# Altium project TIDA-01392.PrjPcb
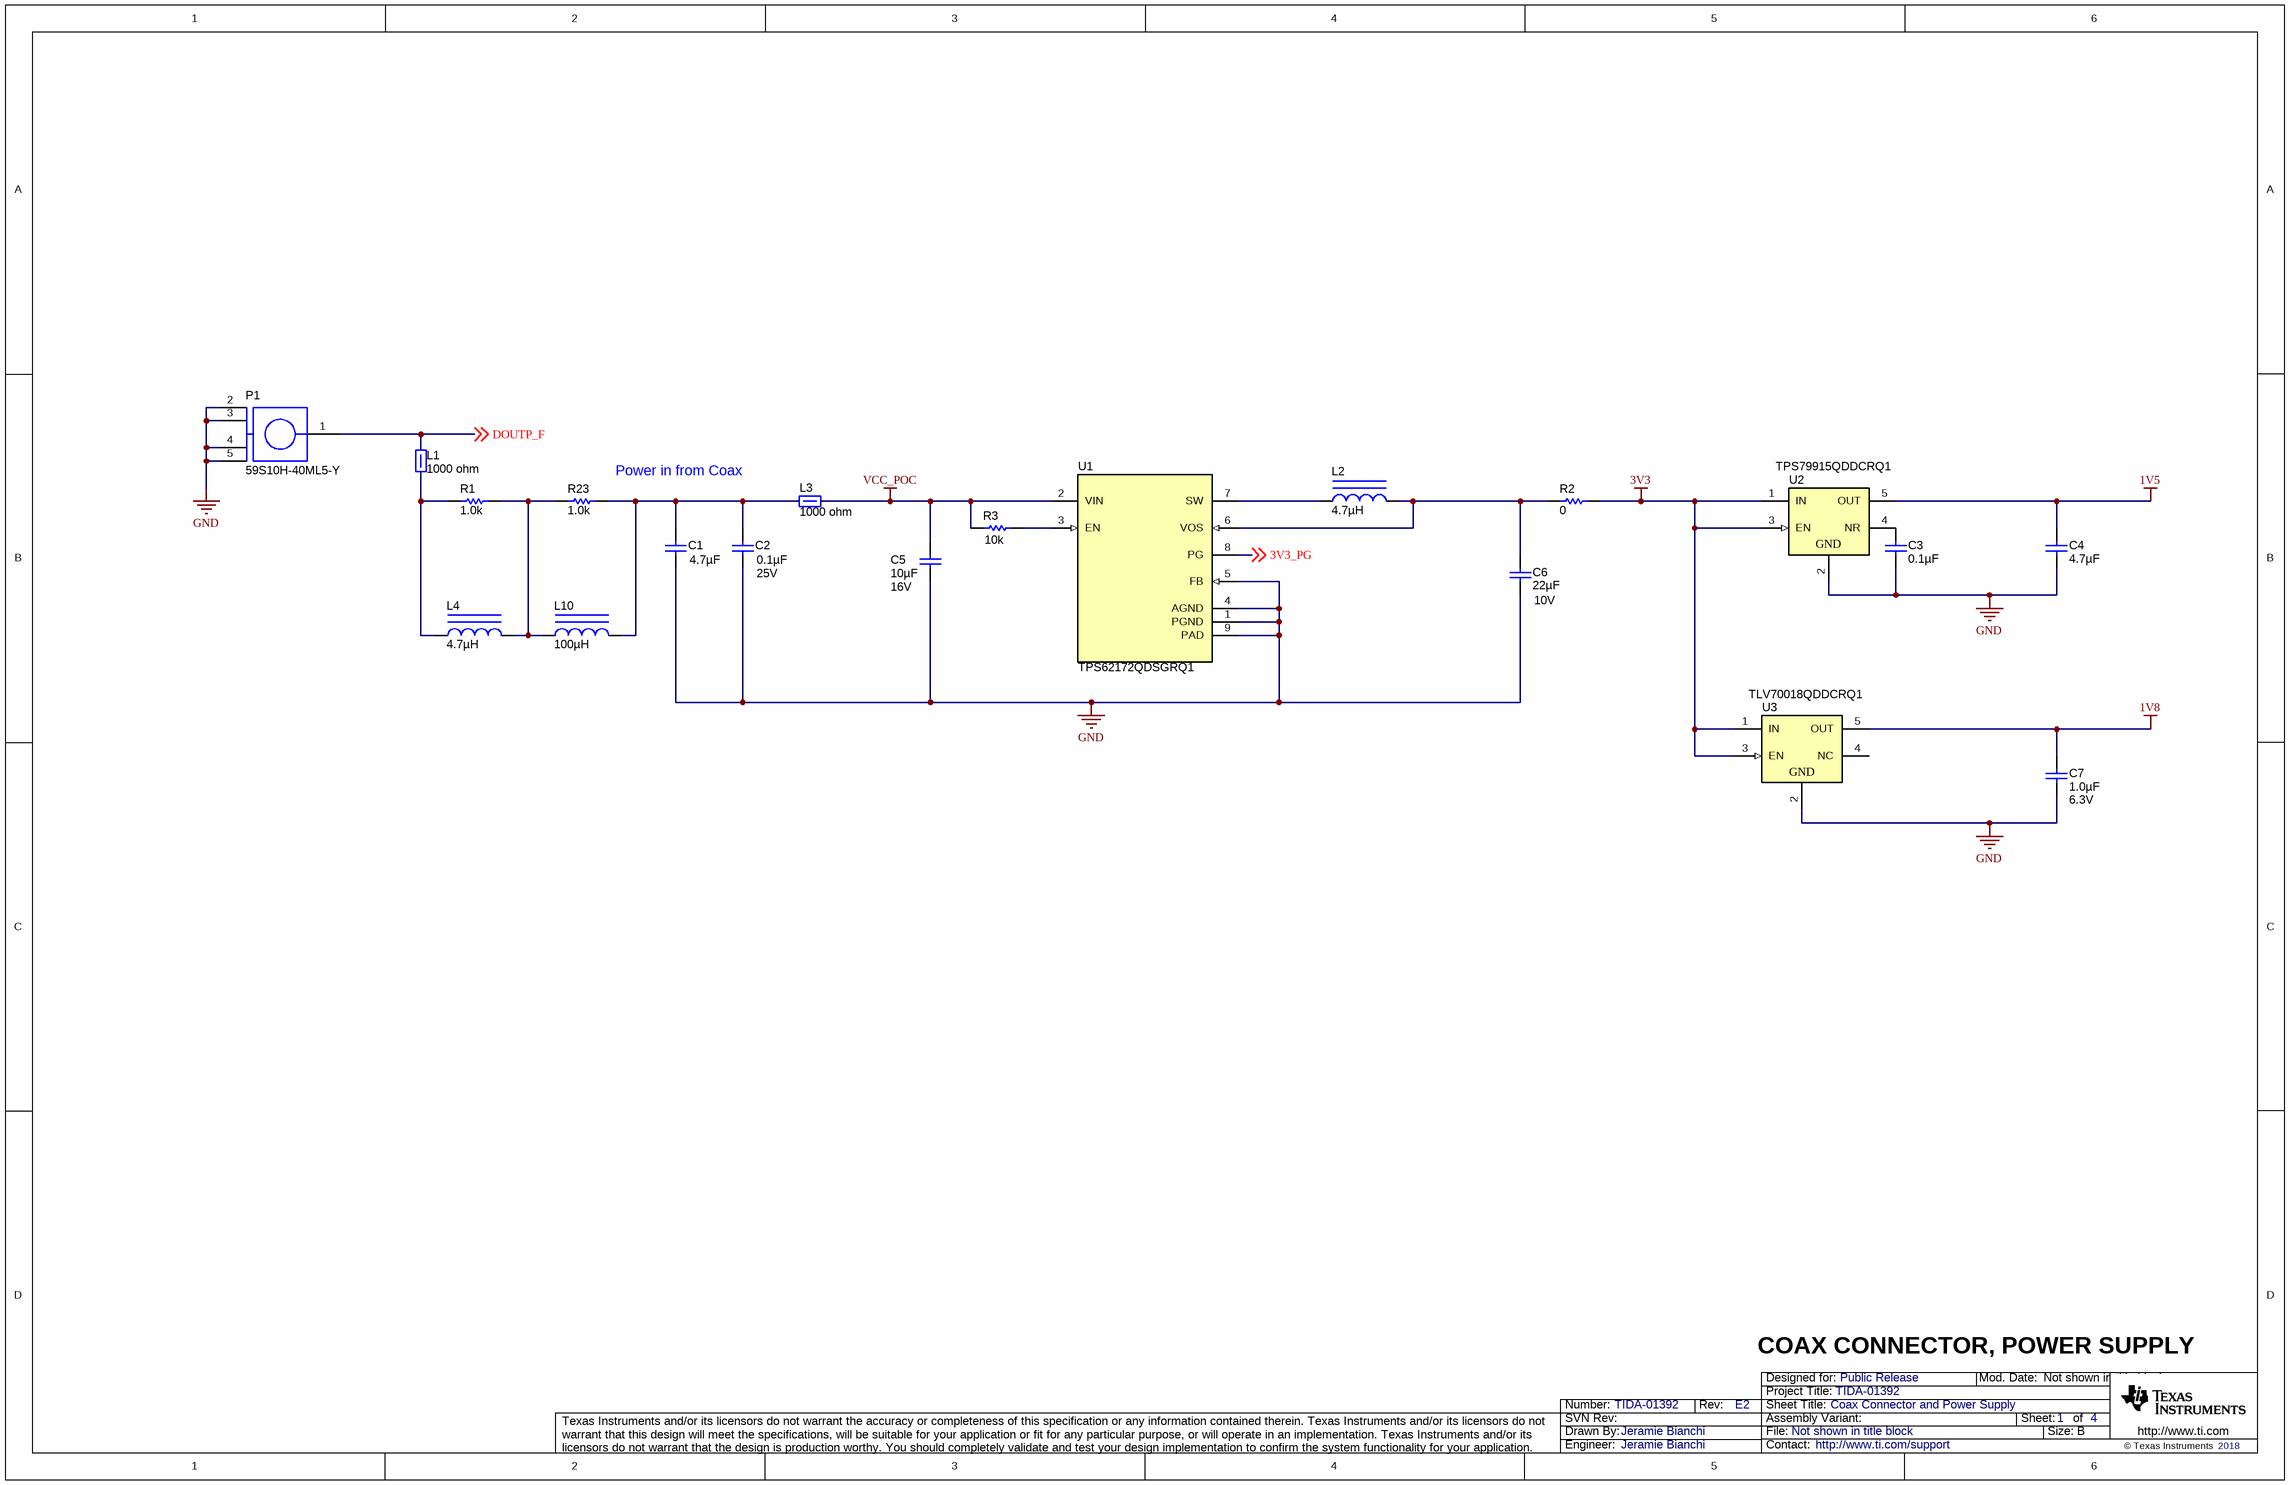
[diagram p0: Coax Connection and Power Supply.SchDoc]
TechSupport: http://www.ti.com/support; SCH_Rev: E2; PRJ_Title: TIDA-01392; PRJ_Number: TIDA-01392; PRJ_Engineer: Jeramie Bianchi; PRJ_Customer: Public Release; PCB_Rev: E2; CopyrightYear: 2018
4 sheets, 91 parts. Net scope: global (net labels, ports and power ports of the same name join across sheets).
Board file: TIDA-01392.PcbDoc
Sheets:
  Coax Connection and Power Supply.SchDoc
  Imager.SchDoc
  Serializer.SchDoc
  HDWR.SchDoc

## Sheet Coax Connection and Power Supply.SchDoc: Coax Connector and Power Supply
size 431 x 279 mm; Date: Not shown in title block; ApprovedBy: Not shown in title block; CheckedBy: Not shown in title block; Author: Not shown in title block; CompanyName: Not shown in title block; DrawnBy: Jeramie Bianchi; Engineer: Not shown in title block; Organization: Not shown in title block; Address1: Not shown in title block; Address2: Not shown in title block; Address3: Not shown in title block; Address4: Not shown in title block; DocumentNumber: 1; Revision: Use project parameter SCH_Rev; SheetNumber: 1; SheetTotal: 4; PageSetup: Record=PageOptions¦CenterHorizontal=True¦CenterVertical=True¦PrintScale=0.62¦XCorrection=1.00¦YCorrection=1.00¦PrintKind=0¦BorderSize=5000000¦LeftOffset=0¦BottomOffset=0¦Orientation=2¦PaperLength=1000¦PaperWidth=1000¦Scale=100¦PaperSource=15¦PrintQuality=600¦MediaType=1¦DitherType=10¦PrintScaleMode=1¦PaperKind=Letter (8.5 x 11")¦PaperIndex=1

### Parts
C1  value 4.7µF  [0805L]  (hidden comment: CGA4J1X7R1E475M125AC)
C2  value 0.1µF  VDC_V: 25V  [0402L]  (hidden comment: C1005X7R1E104K050BB)
C3  ValueDisplayed: 0.1µF  [0402L]  (hidden comment: GRM155R71C104KA88D)
C4  ValueDisplayed: 4.7µF  [0603L]  (hidden comment: CL10B475KQ8NQND)
C5  ValueDisplayed: 10µF  Value2: 16V  [0805_140]  (hidden comment: CL21B106KOQNNNE)
C6  ValueDisplayed: 22µF  VDC_V: 10V  [1206L]  (hidden comment: GRM31CR71A226KE15L)
C7  value 1.0µF  VDC_V: 6.3V  [0402]  (hidden comment: CL05B105KQ5NQNC)
L1  value 1000 ohm  [0603L]  (hidden comment: BLM18AG102SN1D)
L2  ValueDisplayed: 4.7µH  [XPL2010]  (hidden comment: XPL2010-472MLB)
L3  value 1000 ohm  [0603]  (hidden comment: BLM18AG102SN1D)
L4  ValueDisplayed: 4.7µH  [CBC3225]  (hidden comment: CBC3225T4R7MR)
L10  ValueDisplayed: 100µH  [CBC3225]  (hidden comment: CBC3225T101MR)
P1  59S10H-40ML5-Y  [59S10H-40ML5-Y]
R1  ValueDisplayed: 1.0k  [0603]  (hidden comment: CRCW06031K00JNEA)
R2  value 0  [0402L]  (hidden comment: CRCW04020000Z0ED)
R3  value 10k  [0402L]  (hidden comment: CRCW040210K0JNED)
R23  ValueDisplayed: 1.0k  [0603]  (hidden comment: CRCW06031K00JNEA)
U1  TPS62172QDSGRQ1  [DSG0008A]
U2  TPS79915QDDCRQ1  [DDC0005A_N]
U3  TLV70018QDDCRQ1  [DDC0005A_N]

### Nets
1V5: C4.1 U2.5(OUT)
1V8: C7.1 U3.5(OUT)
3V3: R2.1 U2.1(IN) U2.3(EN) U3.1(IN) U3.3(EN)
GND: C1.2 C2.2 C3.2 C4.2 C5.2 C6.2 C7.2 P1.2 P1.3 P1.4 P1.5 U1.1(PGND) U1.4(AGND) U1.5(FB) U1.9(PAD) U2.2(GND) U3.2(GND)
VCC_POC: C5.1 L3.2 R3.2 U1.2(VIN)
3V3_PG: U1.8(PG) ; off-sheet 3V3_PG
DOUTP_F: L1.2 P1.1 ; off-sheet DOUTP_F  [project net DOUT_P]
NetC1_1: C1.1 C2.1 L3.1 L10.2 R23.1
NetC3_1: C3.1 U2.4(NR)
NetC6_1: C6.1 L2.2 R2.2 U1.6(VOS)
NetL1_1: L1.1 L4.1 R1.2
NetL2_1: L2.1 U1.7(SW)
NetL4_2: L4.2 L10.1 R1.1 R23.2
NetR3_1: R3.1 U1.3(EN)

Not connected (* = marked no-connect by the designer): U3 4(NC)

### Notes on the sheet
- Power in from Coax
- COAX CONNECTOR, POWER SUPPLY

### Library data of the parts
C1 = C2012X7R1E474K: CAP, CERM, 4.7uF, 25V, +/-20%, X7R, 0805; Manufacturer: TDK Corporation; Tolerance_%: ±20%
C2 = C1005X7R1E103K: CAP, CERM, 0.1uF, 25V, +/-10%, X7R, 0402; Manufacturer: TDK Corporation; Tolerance_%: ±10%
C3 = GRM155R71C104KA88D: CAP, CERM, 0.1 µF, 16 V, +/- 10%, X7R, 0402; Manufacturer: MuRata; Value: 0.1uF; VDC_V: 16; Tolerance_%: 10; Polarized: N; CompType: Capacitor; U/M: EA; Cap_F: 0.0000001; Value1: Unknown; Value2: 16V; TaMin_C: -55; TaMax_C: 125; Cap_Case: 0402; SizeArea_mm2: 0.5; SizeAreaWB_mm2: 3; SizeX_mm: 1; SizeZ_mm: 0.6; AEC Category: Q200
C4 = CL10B475KQ8NQND: CAP, CERM, 4.7 µF, 6.3 V, +/- 10%, X7R, 0603; Manufacturer: Samsung; Polarized: N; CompType: Capacitor; Value: 4.7uF; U/M: EA; Cap_F: 0.0000047; Tolerance_%: 10; Value1: Unknown; VDC_V: 6.3; Value2: 6.3V; TaMin_C: -55; TaMax_C: 125; Cap_Case: 0603; SizeArea_mm2: 1.28; SizeAreaWB_mm2: 4.68; SizeX_mm: 1.6; SizeY_mm: 0.8; SizeZ_mm: 1; AEC Category: Q200
C5 = CL21B106KOQNNNE: CAP, CERM, 10 µF, 16 V, +/- 10%, X7R, 0805_140; Manufacturer: Samsung Electro-Mechanics; Polarized: N; CompType: Capacitor; Value: 10uF; U/M: EA; Cap_F: 0.00001; Tolerance_%: 10; Value1: Unknown; VDC_V: 16; TaMin_C: -55; TaMax_C: 125; Cap_Case: 0805; AEC Category: Q200
C6 = GRM31CR71A226KE15L: CAP, CERM, 22uF, 10V, +/-10%, X7R, 1206; Manufacturer: MuRata; Polarized: N; CompType: Capacitor; U/M: EA; Cap_F: 0.000022; Tolerance_%: 10; Value1: Unknown; TaMin_C: -55; TaMax_C: 125; Cap_Case: 1206
C7 = Capacitor: CAP CER 1UF 6.3V 10% X7R 0402; Manufacturer: Samsung Electro-Mechanics America, Inc; Polarized: N; U/M: EA
L1 L3 = BLM18AG102SN1D: Ferrite Bead, 1000 ohm @ 100 MHz, 0.4 A, 0603; Manufacturer: MuRata; Imax_A: 0.4; DCR_ohm: 0.5; Value1: 0.5 ohm; Value2: 0.4A; ZTyp@100MHz_Ohm: 1000
L2 = XPL2010-472MLB: Inductor, Shielded, Composite, 4.7 µH, 0.85 A, 0.34 ohm, SMD; Manufacturer: Coilcraft; Value: 4.7uH; Ind_H: 4.7E-6; Imax_A: 0.85; Irms: 1A @ 40C rise; Isat: 0.845A @ 30% inductance drop; DCR_ohm: 0.34; Value2: 0.85A; SizeAreaWB_mm2: 8.7; SizeArea_mm2: 3.8; SizeX_mm: 2; SizeY_mm: 1.9; SizeZ_mm: 1; AEC Category: Q200
L4 = CBC3225T4R7MR: Inductor, Wirewound, 4.7 µH, 1.01 A, 0.1 ohm, SMD; Manufacturer: Taiyo Yuden; Value: 4.7uH; Ind_H: 4.7E-6; Imax_A: 1.01; Irms: 1.04A @ 40C rise; Isat: 1.25A @ 30% inductance drop; DCR_ohm: 0.1; Value1: 0.1 ohm; Value2: 1.01A; SizeAreaWB_mm2: 14.7; SizeArea_mm2: 8; SizeX_mm: 3.2; SizeY_mm: 2.5; SizeZ_mm: 2.7; AEC Category: Q200; AEC Qualified: N; Green_Lifecycle: Active; Green_REACh: Passed
L10 = CBC3225T101MR: Inductor, Wirewound, 100 µH, 0.27 A, 1.4 ohm, SMD; Manufacturer: Taiyo Yuden; Value: 100uH; Ind_H: 100.0E-6; Imax_A: 0.27; Irms: 0.34A @ 40C rise; Isat: 0.27A @ 30% inductance drop; DCR_ohm: 1.4; Value1: 1.4 ohm; Value2: 0.27A; SizeAreaWB_mm2: 14.7; SizeArea_mm2: 8; SizeX_mm: 3.2; SizeY_mm: 2.5; SizeZ_mm: 2.7; AEC Category: Q200; AEC Qualified: N; Green_Lifecycle: Active; Green_REACh: Passed
P1 = 59S10H-40ML5-Y: Straight Plug PCB; Manufacturer: Rosenberger; SymbolVersion: use current date i.e. 2008-05-20; SymbolCreator: Use a-id; CompType: SMA connector; U/M: EA, IN, or GM
R1 R23 = CRCW06031K00JNEA: RES, 1.0 k, 5%, 0.1 W, 0603; Manufacturer: Vishay-Dale; CompType: Resistor; Value: 1.0k; Res_ohm: 1000; Value_Code: 1k00; Tolerance_%: 5; Power_W: 0.1; Value2: 0.1W; VDC_V: 75; TempCo: 200 ppm/C; EIA_Code: E24; U/M: EA; SizeArea_mm2: 1.28; SizeX_mm: 1.6; SizeY_mm: 0.8; SizeZ_mm: 1; AEC Category: Q200; Green_Lifecycle: Active; Green_REACh: Passed
R2 = CRCW04020000Z0ED: RES, 0 ohm, 5%, 0.063W, 0402; Manufacturer: Vishay-Dale; CompType: Resistor; Value_Code: 0000; Tolerance_%: 5; Power_W: 0.063; VDC_V: 50; TempCo: 200 ppm/C; EIA_Code: E24; U/M: EA
R3 = CRCW040210K0JNED: RES, 10k ohm, 5%, 0.063W, 0402; Manufacturer: Vishay-Dale; CompType: Resistor; Res_ohm: 10000; Value_Code: 10k0; Tolerance_%: 5; Power_W: 0.063; VDC_V: 50; TempCo: 200 ppm/C; EIA_Code: E24; U/M: EA
U1 = TPS62172QDSGRQ1: 3-V to17-V 0.5-A Step-Down Converters with DCS-Control™, DSG0008A (WSON-8); Manufacturer: Texas Instruments; Alternate PartNumber: TPS62172QDSGTQ1; SymbolCreator: Altium; SizeArea_mm2: 4; SizeAreaWB_mm2: 9; SizeX_mm: 2; SizeZ_mm: 0.8; CompType: IC; U/M: EA
U2 = TPS79915QDDCRQ1: Single Output High PSRR LDO, 200 mA, Fixed 1.5 V Output, 2.7 to 6.5 V Input, with Low IQ, 5-pin SOT (DDC), -40 to 125 degC, Green (RoHS & no Sb/Br); Alternate PartNumber: Equivalent; Manufacturer: Texas Instruments; Accuracy(%): 2; Fixed Output Options(V): 1.5; Iout(Max)(A): 0.2; Iq(Typ)(mA): 0.04; Rating: Automotive; SubFamily: Single Channel LDO; Vdo(Typ)(mV): 100; Vin(Max)(V): 6.5; Vin(Min)(V): 2.7
U3 = TLV70018QDDCRQ1: Single Output Automotive LDO, 300 mA, Fixed 1.8 V Output, 2 to 5.5 V Input, with Low IQ, 5-pin SOT (DDC), -40 to 125 degC, Green (RoHS & no Sb/Br); Manufacturer: Texas Instruments; Alternate PartNumber: Equivalent; Accuracy(%): 2; Fixed Output Options(V): 1.8; Iout(Max)(A): 0.2; Iq(Typ)(mA): 0.03; SubFamily: Single Channel LDO; Vdo(Typ)(mV): 175; Vin(Max)(V): 5.5

## Sheet Imager.SchDoc: Image Sensor
size 431 x 279 mm; Date: Not shown in title block; ApprovedBy: Not shown in title block; CheckedBy: Not shown in title block; Author: Not shown in title block; CompanyName: Not shown in title block; DrawnBy: Jeramie Bianchi; Engineer: Not shown in title block; Organization: Not shown in title block; Address1: Not shown in title block; Address2: Not shown in title block; Address3: Not shown in title block; Address4: Not shown in title block; DocumentNumber: 2; Revision: Use project parameter SCH_Rev; SheetNumber: 2; SheetTotal: 4; PageSetup: Record=PageOptions¦CenterHorizontal=True¦CenterVertical=True¦PrintScale=0.96¦XCorrection=1.00¦YCorrection=1.00¦PrintKind=0¦BorderSize=5000000¦LeftOffset=0¦BottomOffset=0¦Orientation=2¦PaperLength=4318¦PaperWidth=2794¦Scale=100¦PaperSource=15¦PrintQuality=600¦MediaType=1¦DitherType=10¦PrintScaleMode=1¦PaperKind=Tabloid (11 x 17")¦PaperIndex=17
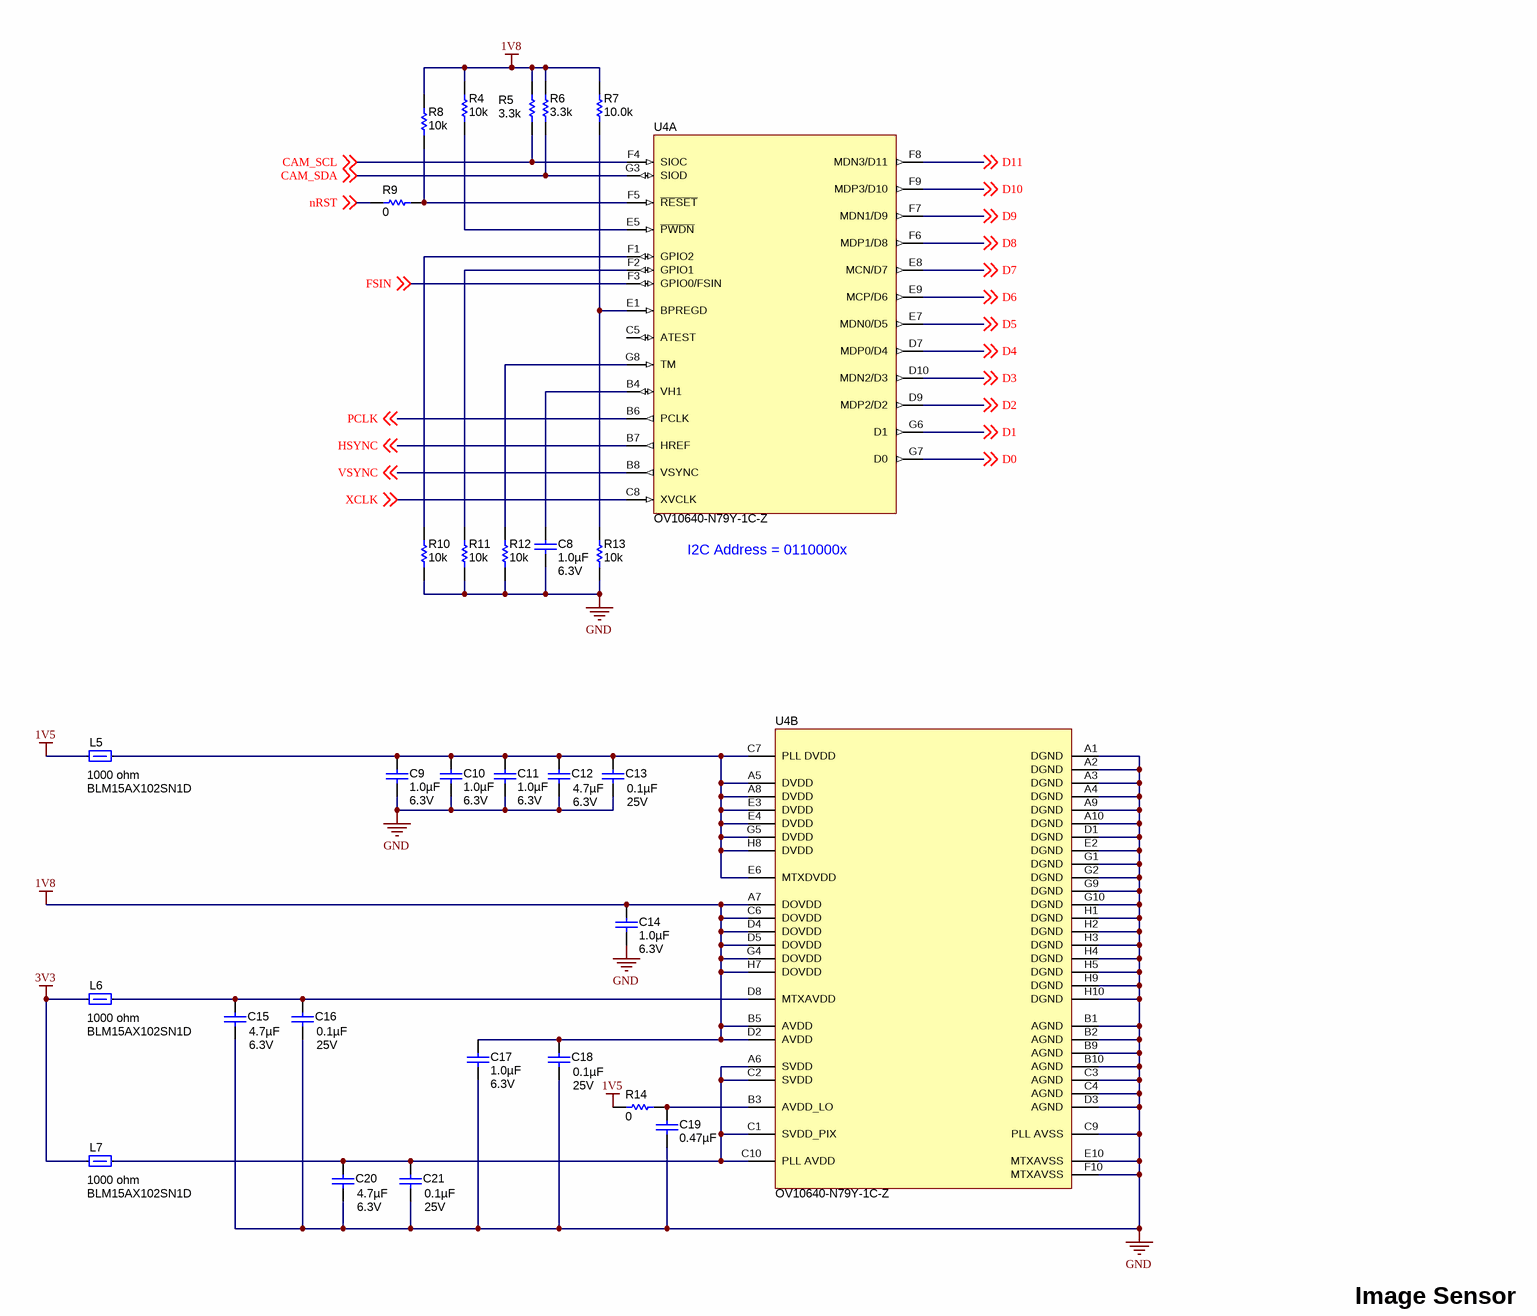
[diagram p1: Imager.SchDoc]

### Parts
C8  value 1.0µF  VDC_V: 6.3V  [0402L]  (hidden comment: CL05B105KQ5NQNC)
C9  value 1.0µF  VDC_V: 6.3V  [0402L]  (hidden comment: CL05B105KQ5NQNC)
C10  value 1.0µF  VDC_V: 6.3V  [0402L]  (hidden comment: CL05B105KQ5NQNC)
C11  value 1.0µF  VDC_V: 6.3V  [0402L]  (hidden comment: CL05B105KQ5NQNC)
C12  value 4.7µF  VDC_V: 6.3V  [0603L]  (hidden comment: CL10B475KQ8NQNC)
C13  value 0.1µF  VDC_V: 25V  [0402L]  (hidden comment: C1005X7R1E104K050BB)
C14  value 1.0µF  VDC_V: 6.3V  [0402L]  (hidden comment: CL05B105KQ5NQNC)
C15  value 4.7µF  VDC_V: 6.3V  [0603L]  (hidden comment: CL10B475KQ8NQNC)
C16  value 0.1µF  VDC_V: 25V  [0402L]  (hidden comment: C1005X7R1E104K050BB)
C17  value 1.0µF  VDC_V: 6.3V  [0402L]  (hidden comment: CL05B105KQ5NQNC)
C18  value 0.1µF  VDC_V: 25V  [0402L]  (hidden comment: C1005X7R1E104K050BB)
C19  ValueDisplayed: 0.47µF  [0402]  (hidden comment: GRM155R60J474KE19D)
C20  value 4.7µF  VDC_V: 6.3V  [0603L]  (hidden comment: CL10B475KQ8NQNC)
C21  value 0.1µF  VDC_V: 25V  [0402L]  (hidden comment: C1005X7R1E104K050BB)
L5  value 1000 ohm  [0402]  (hidden comment: BLM15AX102SN1D)
L6  value 1000 ohm  [0402]  (hidden comment: BLM15AX102SN1D)
L7  value 1000 ohm  [0402]  (hidden comment: BLM15AX102SN1D)
R4  value 10k  [0402L]  (hidden comment: CRCW040210K0JNED)
R5  value 3.3k  [0603L]  (hidden comment: CRCW06033K30JNEA)
R6  value 3.3k  [0603L]  (hidden comment: CRCW06033K30JNEA)
R7  ValueDisplayed: 10.0k  [0402L]  (hidden comment: CRCW040210K0DHEDP)
R8  value 10k  [0402L]  (hidden comment: CRCW040210K0JNED)
R9  value 0  [0402L]  (hidden comment: CRCW04020000Z0ED)
R10  value 10k  [0402L]  (hidden comment: CRCW040210K0JNED)
R11  value 10k  [0402L]  (hidden comment: CRCW040210K0JNED)
R12  value 10k  [0402L]  (hidden comment: CRCW040210K0JNED)
R13  value 10k  [0402L]  (hidden comment: CRCW040210K0JNED)
R14  value 0  [0402L]  (hidden comment: CRCW04020000Z0ED)
U4  OV10640-N79Y-1C-Z  [OVT_10640_aCSP]  (parts A,B of 2)

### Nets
1V5: L5.1 R14.2
1V8: C14.1 C17.1 C18.1 R4.2 R5.2 R6.2 R7.2 R8.2 U4.A7(DOVDD) U4.B5(AVDD) U4.C6(DOVDD) U4.D2(AVDD) U4.D4(DOVDD) U4.D5(DOVDD) U4.G4(DOVDD) U4.H7(DOVDD)
3V3: L6.1 L7.1
GND: C8.2 C9.2 C10.2 C11.2 C12.2 C13.2 C14.2 C15.2 C16.2 C17.2 C18.2 C19.2 C20.2 C21.2 R10.1 R11.1 R12.1 R13.1 U4.A1(DGND) U4.A2(DGND) U4.A3(DGND) U4.A4(DGND) U4.A9(DGND) U4.A10(DGND) U4.B1(AGND) U4.B2(AGND) U4.B9(AGND) U4.B10(AGND) U4.C3(AGND) U4.C4(AGND) U4.C9(PLL_AVSS) U4.D1(DGND) U4.D3(AGND) U4.E2(DGND) U4.E10(MTXAVSS) U4.F10(MTXAVSS) U4.G1(DGND) U4.G2(DGND) U4.G9(DGND) U4.G10(DGND) U4.H1(DGND) U4.H2(DGND) U4.H3(DGND) U4.H4(DGND) U4.H5(DGND) U4.H9(DGND) U4.H10(DGND)
CAM_SCL: R5.1 U4.F4(SIOC) ; off-sheet CAM_SCL
CAM_SDA: R6.1 U4.G3(SIOD) ; off-sheet CAM_SDA
D0: U4.G7(D0) ; off-sheet D0
D1: U4.G6(D1) ; off-sheet D1
D2: U4.D9(MDP2/D2) ; off-sheet D2
D3: U4.D10(MDN2/D3) ; off-sheet D3
D4: U4.D7(MDP0/D4) ; off-sheet D4
D5: U4.E7(MDN0/D5) ; off-sheet D5
D6: U4.E9(MCP/D6) ; off-sheet D6
D7: U4.E8(MCN/D7) ; off-sheet D7
D8: U4.F6(MDP1/D8) ; off-sheet D8
D9: U4.F7(MDN1/D9) ; off-sheet D9
D10: U4.F9(MDP3/D10) ; off-sheet D10
D11: U4.F8(MDN3/D11) ; off-sheet D11
FSIN: U4.F3(GPIO0/FSIN) ; off-sheet FSIN
HSYNC: U4.B7(HREF) ; off-sheet HSYNC
nRST: R9.2 ; off-sheet nRST
PCLK: U4.B6(PCLK) ; off-sheet PCLK
VSYNC: U4.B8(VSYNC) ; off-sheet VSYNC
XCLK: U4.C8(XVCLK) ; off-sheet XCLK
NetC8_1: C8.1 U4.B4(VH1)
NetC9_1: C9.1 C10.1 C11.1 C12.1 C13.1 L5.2 U4.A5(DVDD) U4.A8(DVDD) U4.C7(PLL_DVDD) U4.E3(DVDD) U4.E4(DVDD) U4.E6(MTXDVDD) U4.G5(DVDD) U4.H8(DVDD)
NetC15_1: C15.1 C16.1 L6.2 U4.D8(MTXAVDD)
NetC19_1: C19.1 R14.1 U4.B3(AVDD_LO)
NetC20_1: C20.1 C21.1 L7.2 U4.A6(SVDD) U4.C1(SVDD_PIX) U4.C2(SVDD) U4.C10(PLL_AVDD)
NetR4_1: R4.1 U4.E5(~{PWDN})
NetR7_1: R7.1 R13.2 U4.E1(BPREGD)
NetR8_1: R8.1 R9.1 U4.F5(~{RESET})
NetR10_2: R10.2 U4.F1(GPIO2)
NetR11_2: R11.2 U4.F2(GPIO1)
NetR12_2: R12.2 U4.G8(TM)

Not connected (* = marked no-connect by the designer): U4 C5(ATEST)

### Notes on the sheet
- (near U4) I2C Address = 0110000x
- Image Sensor

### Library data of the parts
C8-C11 C14 C17 = Capacitor: as C7 on sheet Coax Connection and Power Supply
C12 C15 C20 = Capacitor: CAP CER 4.7UF 6.3V 10% X7R 0603; Manufacturer: Samsung Electro-Mechanics America, Inc; Polarized: N; U/M: EA
C13 C16 C18 C21 = C1005X7R1E103K: as C2 on sheet Coax Connection and Power Supply
C19 = GRM155R60J474KE19D: CAP, CERM, 0.47 µF, 6.3 V, +/- 10%, X5R, 0402; Manufacturer: MuRata; Polarized: N; CompType: Capacitor; Value: 0.47uF; U/M: EA; Cap_F: 0.00000047; Tolerance_%: 10; Value1: Unknown; VDC_V: 6.3; Value2: 6.3V; TaMin_C: -55; TaMax_C: 85; AEC Category: Q200
L5-L7 = BLM15AX102SN1D: Ferrite Bead, 1000 ohm @ 100 MHz, 0.35 A, 0402; Manufacturer: MuRata; Imax_A: 0.35; DCR_ohm: 0.49; Value1: 0.49 ohm; Value2: 0.35A; ZTyp@100MHz_Ohm: 1000
R4 R8 R10-R13 = CRCW040210K0JNED: as R3 on sheet Coax Connection and Power Supply
R5 R6 = CRCW06033K30JNEA: RES, 3.3k ohm, 5%, 0.1W, 0603; Manufacturer: Vishay-Dale; CompType: Resistor; Res_ohm: 3300; Value_Code: 3k30; Tolerance_%: 5; Power_W: 0.1; VDC_V: 75; TempCo: 200 ppm/C; EIA_Code: E24; U/M: EA
R7 = CRCW040210K0DHEDP: RES, 10.0 k, 0.5%, 0.063 W, 0402; Manufacturer: Vishay-Dale; CompType: Resistor; Value: 10.0k; Res_ohm: 10000; Value_Code: 10k0; Tolerance_%: 0.5; Power_W: 0.063; Value2: 0.063W; VDC_V: 50; TempCo: 50 ppm/C; EIA_Code: E192; U/M: EA; SizeX_mm: 1; SizeZ_mm: 0.6; AEC Category: Q200
R9 R14 = CRCW04020000Z0ED: as R2 on sheet Coax Connection and Power Supply
U4 = OV10640-N79Y-1C-Z: 1/2.56" color CMOS 1.3 megapixel HDR HD image sensor, BGA78; Manufacturer: OmniVision Technologies; SymbolCreator: a0412235

## Sheet Serializer.SchDoc: Serializer
size 431 x 279 mm; Date: Not shown in title block; ApprovedBy: Not shown in title block; CheckedBy: Not shown in title block; Author: Not shown in title block; CompanyName: Not shown in title block; DrawnBy: Jeramie Bianchi; Engineer: Not shown in title block; Organization: Not shown in title block; Address1: Not shown in title block; Address2: Not shown in title block; Address3: Not shown in title block; Address4: Not shown in title block; DocumentNumber: 3; Revision: Use project parameter SCH_Rev; SheetNumber: 3; SheetTotal: 4; PageSetup: Record=PageOptions¦CenterHorizontal=True¦CenterVertical=True¦PrintScale=0.96¦XCorrection=1.00¦YCorrection=1.00¦PrintKind=0¦BorderSize=5000000¦LeftOffset=0¦BottomOffset=0¦Orientation=2¦PaperLength=4318¦PaperWidth=2794¦Scale=100¦PaperSource=15¦PrintQuality=600¦MediaType=1¦DitherType=10¦PrintScaleMode=1¦PaperKind=Tabloid (11 x 17")¦PaperIndex=17
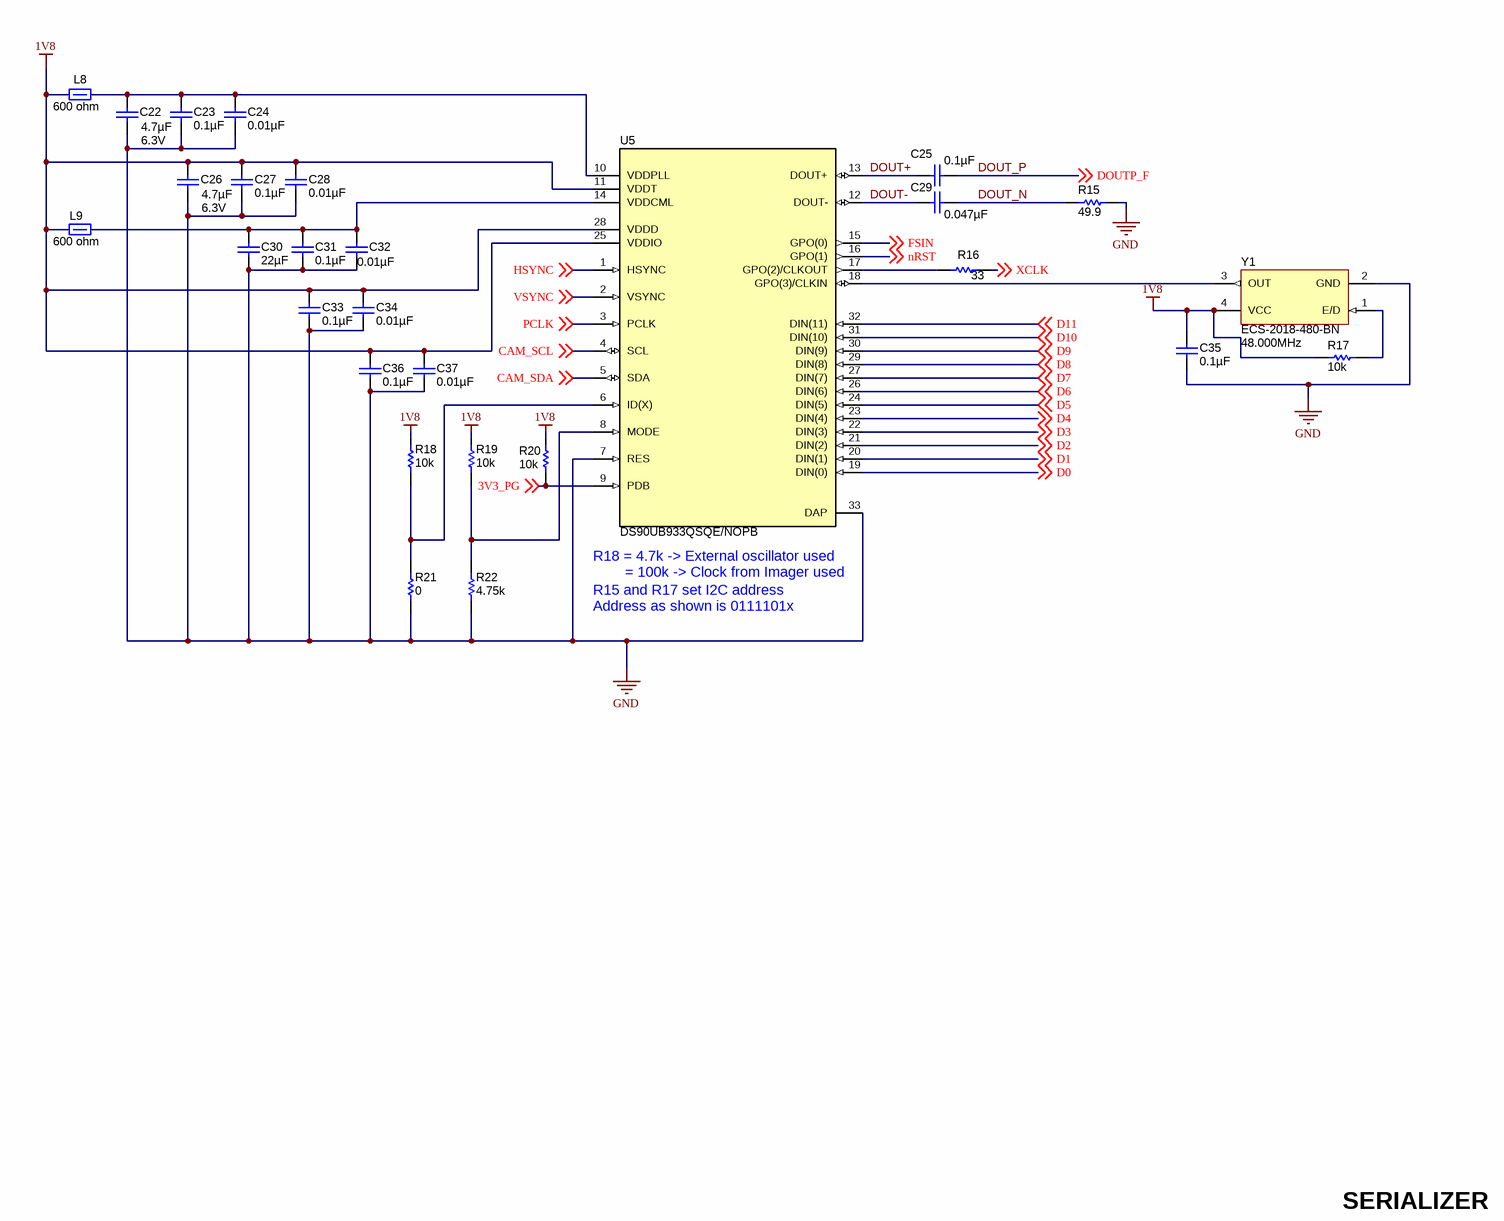
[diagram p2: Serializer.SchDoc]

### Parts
C22  value 4.7µF  VDC_V: 6.3V  [0603L]  (hidden comment: CL10B475KQ8NQNC)
C23  ValueDisplayed: 0.1µF  [0402L]  (hidden comment: GRM155R71C104KA88D)
C24  ValueDisplayed: 0.01µF  [0402L]  (hidden comment: GRM155R71C103KA01D)
C25  ValueDisplayed: 0.1µF  [0402L]  (hidden comment: C1005X7R1H104K050BE)
C26  value 4.7µF  VDC_V: 6.3V  [0603L]  (hidden comment: CL10B475KQ8NQNC)
C27  ValueDisplayed: 0.1µF  [0402L]  (hidden comment: GRM155R71C104KA88D)
C28  ValueDisplayed: 0.01µF  [0402L]  (hidden comment: GRM155R71C103KA01D)
C29  ValueDisplayed: 0.047µF  [0402L]  (hidden comment: C1005X7R1H473K050BB)
C30  ValueDisplayed: 22µF  [1206L]  (hidden comment: GRM31CR71A226KE15L)
C31  ValueDisplayed: 0.1µF  [0402L]  (hidden comment: GRM155R71C104KA88D)
C32  ValueDisplayed: 0.01µF  [0402L]  (hidden comment: GRM155R71C103KA01D)
C33  ValueDisplayed: 0.1µF  [0402L]  (hidden comment: GRM155R71C104KA88D)
C34  ValueDisplayed: 0.01µF  [0402L]  (hidden comment: GRM155R71C103KA01D)
C35  ValueDisplayed: 0.1µF  [0402L]  (hidden comment: GRM155R71C104KA88D)
C36  ValueDisplayed: 0.1µF  [0402L]  (hidden comment: GRM155R71C104KA88D)
C37  ValueDisplayed: 0.01µF  [0402L]  (hidden comment: GRM155R71C103KA01D)
L8  value 600 ohm  [0603]  (hidden comment: BLM18KG601SN1D)
L9  value 600 ohm  [0603]  (hidden comment: BLM18KG601SN1D)
R15  value 49.9  [0402L]  (hidden comment: CRCW040249R9FKED)
R16  value 33  [0402L]  (hidden comment: CRCW040233R0JNED)
R17  value 10k  [0402L]  (hidden comment: CRCW040210K0JNED)
R18  value 10k  [0402L]  (hidden comment: CRCW040210K0JNED)
R19  value 10k  [0402L]  (hidden comment: CRCW040210K0JNED)
R20  value 10k  [0402L]  (hidden comment: CRCW040210K0JNED)
R21  value 0  [0402L]  (hidden comment: CRCW04020000Z0ED)
R22  value 4.75k  [0402L]
U5  DS90UB933QSQE/NOPB  [RTV0032A]
Y1  ECS-2018-480-BN  Frequency: 48.000MHz  [ECS_2018]

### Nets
1V8: C26.1 C27.1 C28.1 C33.1 C34.1 C35.1 C36.1 C37.1 L8.1 L9.1 R17.2 R18.2 R19.2 R20.2 U5.11(VDDT) U5.25(VDDIO) U5.28(VDDD) Y1.4(VCC)
GND: C22.2 C23.2 C24.2 C26.2 C27.2 C28.2 C30.2 C31.2 C32.2 C33.2 C34.2 C35.2 C36.2 C37.2 R15.2 R21.1 R22.1 U5.7(RES) U5.33(DAP) Y1.2(GND)
3V3_PG: R20.1 U5.9(PDB) ; off-sheet 3V3_PG
CAM_SCL: U5.4(SCL) ; off-sheet CAM_SCL
CAM_SDA: U5.5(SDA) ; off-sheet CAM_SDA
D0: U5.19(DIN(0)) ; off-sheet D0
D1: U5.20(DIN(1)) ; off-sheet D1
D2: U5.21(DIN(2)) ; off-sheet D2
D3: U5.22(DIN(3)) ; off-sheet D3
D4: U5.23(DIN(4)) ; off-sheet D4
D5: U5.24(DIN(5)) ; off-sheet D5
D6: U5.26(DIN(6)) ; off-sheet D6
D7: U5.27(DIN(7)) ; off-sheet D7
D8: U5.29(DIN(8)) ; off-sheet D8
D9: U5.30(DIN(9)) ; off-sheet D9
D10: U5.31(DIN(10)) ; off-sheet D10
D11: U5.32(DIN(11)) ; off-sheet D11
DOUT+: C25.2 U5.13(DOUT+)
DOUT-: C29.2 U5.12(DOUT-)
DOUT_N: C29.1 R15.1
DOUT_P: C25.1 ; off-sheet DOUTP_F  [also labelled DOUTP_F]
FSIN: U5.15(GPO(0)) ; off-sheet FSIN
HSYNC: U5.1(HSYNC) ; off-sheet HSYNC
nRST: U5.16(GPO(1)) ; off-sheet nRST
PCLK: U5.3(PCLK) ; off-sheet PCLK
VSYNC: U5.2(VSYNC) ; off-sheet VSYNC
XCLK: R16.2 ; off-sheet XCLK
NetC22_1: C22.1 C23.1 C24.1 L8.2 U5.10(VDDPLL)
NetC30_1: C30.1 C31.1 C32.1 L9.2 U5.14(VDDCML)
NetR16_1: R16.1 U5.17(GPO(2)/CLKOUT)
NetR17_1: R17.1 Y1.1(E/D)
NetR18_1: R18.1 R21.2 U5.6(ID(X))
NetR19_1: R19.1 R22.2 U5.8(MODE)
NetU5_18: U5.18(GPO(3)/CLKIN) Y1.3(OUT)

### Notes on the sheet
- (near U5) R18 = 4.7k -> External oscillator used
  = 100k -> Clock from Imager used
- R15 and R17 set I2C address
  Address as shown is 0111101x
- SERIALIZER

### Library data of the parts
C22 C26 = Capacitor: as C12 on sheet Imager
C23 C27 C31 C33 C35 C36 = GRM155R71C104KA88D: CAP, CERM, 0.1uF, 16V, +/-10%, X7R, 0402; Manufacturer: MuRata; Polarized: N; CompType: Capacitor; U/M: EA; Cap_F: 0.0000001; Tolerance_%: 10; Value1: Unknown; VDC_V: 16; TaMin_C: -55; TaMax_C: 125; Cap_Case: 0402
C24 C28 C32 C34 C37 = GRM155R71C103KA01D: CAP, CERM, 0.01uF, 16V, +/-10%, X7R, 0402; Manufacturer: MuRata; Polarized: N; CompType: Capacitor; U/M: EA; Cap_F: 0.00000001; Tolerance_%: 10; Value1: Unknown; VDC_V: 16; TaMin_C: -55; TaMax_C: 125; Cap_Case: 0402
C25 = C1005X7R1H104K: CAP, CERM, 0.1uF, 50V, +/-10%, C0G/NP0, 0402; Manufacturer: TDK; Polarized: N; CompType: Capacitor; U/M: EA; Cap_F: 0.0000001; Tolerance_%: 10; Value1: Unknown; VDC_V: 50; TaMin_C: -55; TaMax_C: 125; Cap_Case: 0402
C29 = C1005X7R1H473K050BB: CAP, CERM, 0.047 µF, 50 V, +/- 10%, X7R, 0402; Manufacturer: TDK; Polarized: N; CompType: Capacitor; Value: 0.047uF; U/M: EA; Cap_F: 0.000000047; Tolerance_%: 10; ESR_ohm: 0.06407; Value1: 0.06407 ohm; VDC_V: 50; Value2: 50V; IRMS_A: 0.646122; TaMin_C: -55; TaMax_C: 125; Cap_Case: 0402; SizeArea_mm2: 0.5; SizeAreaWB_mm2: 3; SizeX_mm: 1; SizeZ_mm: 0.6; AEC Category: Q200
C30 = GRM31CR71A226KE15L: as C6 on sheet Coax Connection and Power Supply
L8 L9 = BLM18KG601SN1D: 1.3A Ferrite Bead, 600 ohm @ 100MHz, SMD; Manufacturer: MuRata; Imax_A: 1.3; Irms: 1.3A @ C rise; Isat: 1.3A @ % inductance drop; DCR_ohm: 0.15; Value1: 0.15 ohm; ZTyp@100MHz_Ohm: 600; U/M: EA
R15 = CRCW040249R9FKED: RES, 49.9 ohm, 1%, 0.063W, 0402; Manufacturer: Vishay-Dale; CompType: Resistor; Value_Code: 49R9; Tolerance_%: 1; Power_W: 0.063; VDC_V: 50; TempCo: 100 ppm/C; EIA_Code: E96; U/M: EA
R16 = CRCW040233R0JNED: RES, 33 ohm, 5%, 0.063W, 0402; Manufacturer: Vishay-Dale; CompType: Resistor; Value_Code: 33R0; Tolerance_%: 5; Power_W: 0.063; VDC_V: 50; TempCo: 200 ppm/C; EIA_Code: E24; U/M: EA
R17-R20 = CRCW040210K0JNED: as R3 on sheet Coax Connection and Power Supply
R21 = CRCW04020000Z0ED: as R2 on sheet Coax Connection and Power Supply
R22 = CRCW04024K75FKED: RES, 4.75k ohm, 1%, 0.063W, 0402; Manufacturer: Vishay-Dale; CompType: Resistor; Res_ohm: 4750; Value_Code: 4k75; Tolerance_%: 1; Power_W: 0.063; VDC_V: 50; TempCo: 100 ppm/C; EIA_Code: E96; U/M: EA
U5 = DS90UB933QSQE/NOPB: 10-100MHz 10/12- Bit DC-Balanced FPD-Link III Serializer and Deserializer with Bidirectional Control Channel, RTV0032A (WQFN-32); Alternate Manufacturer: Texas Instruments; SymbolCreator: x0208325; CompType: IC; U/M: EA; SizeArea_mm2: 25; SizeAreaWB_mm2: 49; SizeX_mm: 5; SizeZ_mm: 0.8
Y1 = ECS-2018-480-BN: XO, 48.000MHz, 1.8V, SMD; Manufacturer: ECS Inc.; SymbolCreator: a0411947; CompType: Oscillator; U/M: EA; TaMin_C: -40; TaMax_C: 85; Frequency Stability: ±50ppm

## Sheet HDWR.SchDoc: Hardware
size 431 x 279 mm; Date: Not shown in title block; ApprovedBy: Not shown in title block; CheckedBy: Not shown in title block; Author: Not shown in title block; CompanyName: Not shown in title block; DrawnBy: Jeramie Bianchi; Engineer: Not shown in title block; Organization: Not shown in title block; Address1: Not shown in title block; Address2: Not shown in title block; Address3: Not shown in title block; Address4: Not shown in title block; DocumentNumber: 4; Revision: Use project parameter SCH_Rev; SheetNumber: 4; SheetTotal: 4; PageSetup: Record=PageOptions¦CenterHorizontal=True¦CenterVertical=True¦PrintScale=1.00¦XCorrection=1.00¦YCorrection=1.00¦PrintKind=0¦BorderSize=5000000¦LeftOffset=0¦BottomOffset=0¦Orientation=2¦PaperLength=1000¦PaperWidth=1000¦Scale=100¦PaperSource=15¦PrintQuality=600¦MediaType=1¦DitherType=10¦PaperKind=Letter¦PrintScaleMode=1
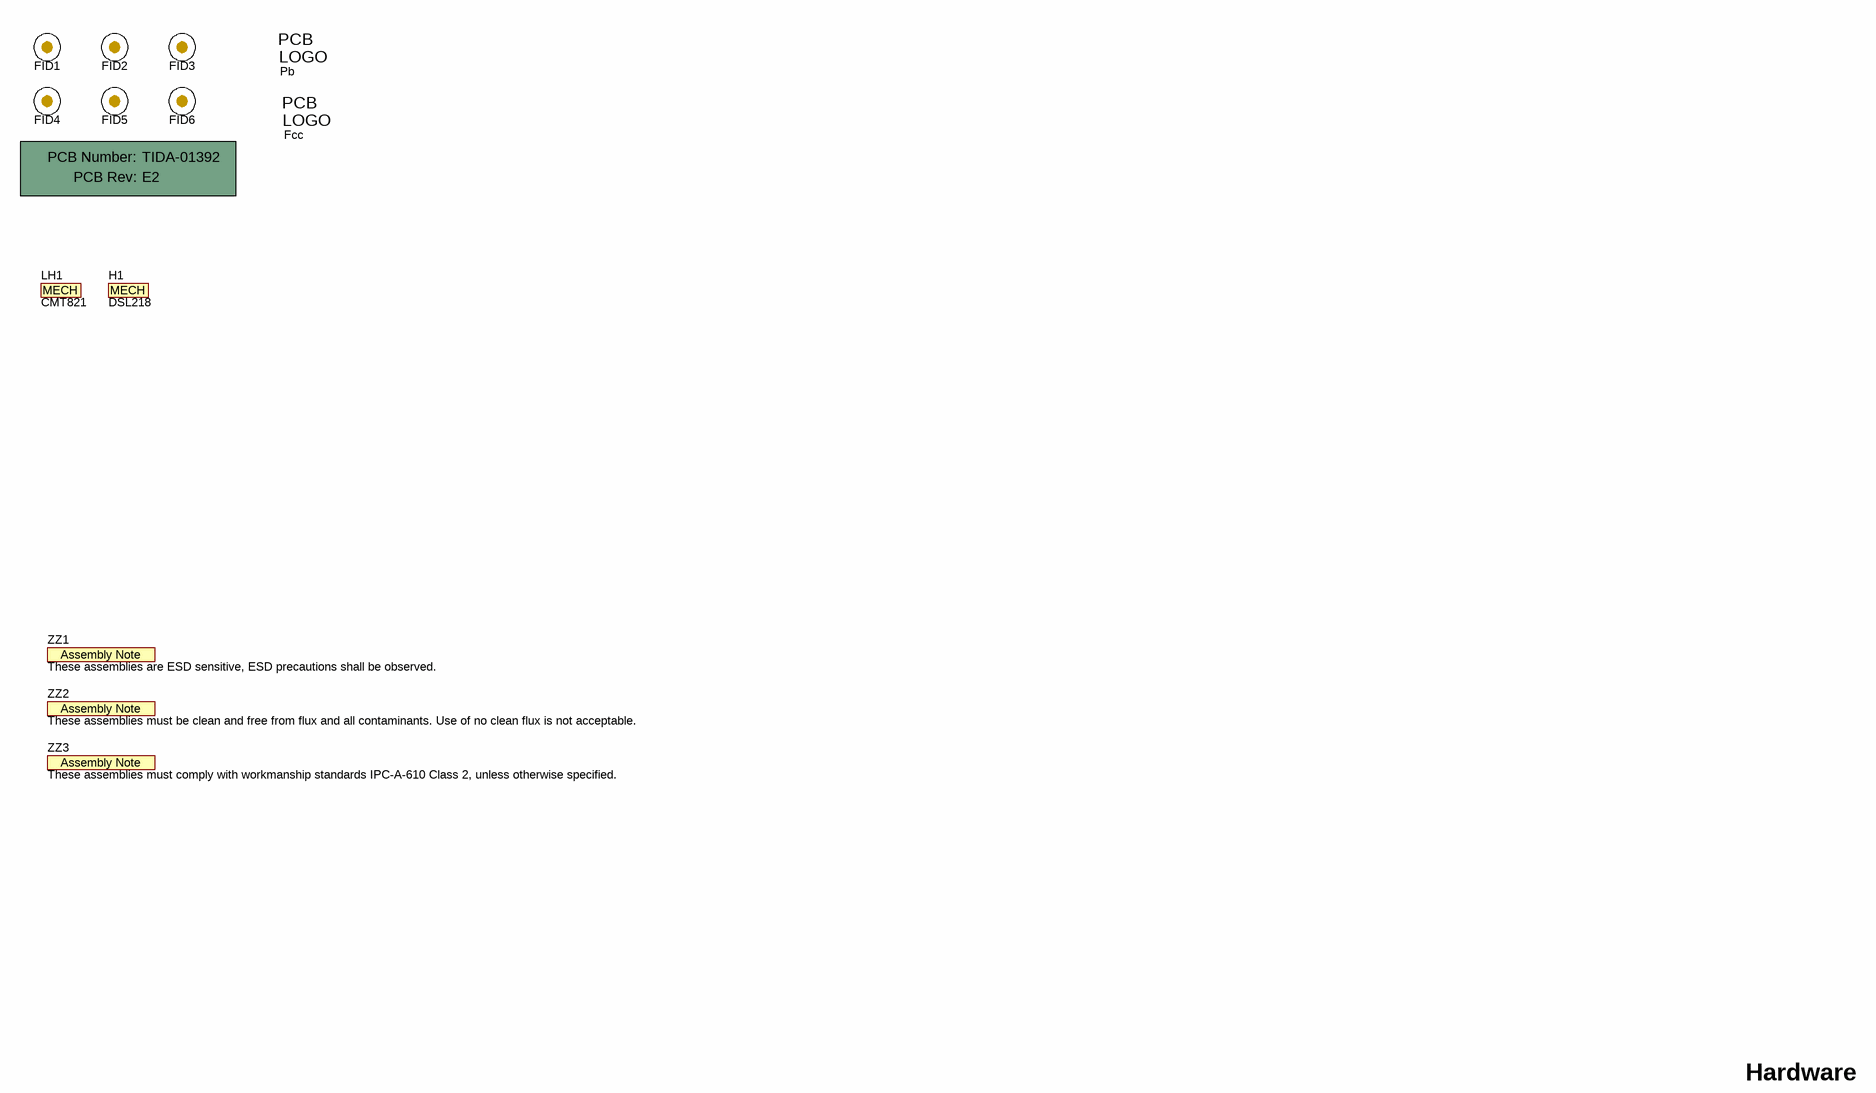
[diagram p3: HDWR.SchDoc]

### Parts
!PCB1  Printed Circuit Board  (value not drawn)  (mechanical)
Fcc  FCC disclaimer  [FCC_disclaimer]  (value not drawn)  (no BOM)
FID1  Fiducial  [Fiducial10-20]  (value not drawn)
FID2  Fiducial  [Fiducial10-20]  (value not drawn)
FID3  Fiducial  [Fiducial10-20]  (value not drawn)
FID4  Fiducial  [Fiducial10-20]  (value not drawn)
FID5  Fiducial  [Fiducial10-20]  (value not drawn)
FID6  Fiducial  [Fiducial10-20]  (value not drawn)
H1  DSL218  (mechanical)
LH1  CMT821  [CMT821]
Pb  Pb-Free Symbol  [Pb-Free_Overlay_Medium]  (value not drawn)  (no BOM)
ZZ1  These assemblies are ESD sensitive, ESD precautions shall be observed.  [AssemblyNote]  (no BOM)
ZZ2  These assemblies must be clean and free from flux and all contaminants. Use of no clean flux is not acceptable.  [AssemblyNote]  (no BOM)
ZZ3  These assemblies must comply with workmanship standards IPC-A-610 Class 2, unless otherwise specified.  [AssemblyNote]  (no BOM)

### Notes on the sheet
- Hardware

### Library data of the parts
!PCB1 = PCB: Manufacturer: Any; PartNumber: TIDA-01392; SymbolCreator: a0412235
Fcc = FCC_disclaimer: SymbolCreator: a0412235
FID1-FID6 = Fiducial: Fiducial mark.  There is nothing to buy or mount.; SymbolCreator: codlsc
H1 = MechPart: Lens; Manufacturer: Sunex, Inc; SymbolCreator: codlsc; CompType: Mechanical; U/M: EA
LH1 = CMT821: Sunex Lens Holder; Manufacturer: Sunex Inc.
Pb = Pb-Free: SymbolCreator: a0412235
ZZ1-ZZ3 = AssemblyNote: SymbolCreator: codlsc

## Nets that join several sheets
1V5: Coax Connection and Power Supply (C4.1 U2.5), Imager (L5.1 R14.2)
1V8: Coax Connection and Power Supply (C7.1 U3.5), Imager (16 pins), Serializer (18 pins)
3V3: Coax Connection and Power Supply (5 pins), Imager (L6.1 L7.1)
GND: Coax Connection and Power Supply (17 pins), Imager (47 pins), Serializer (20 pins)
3V3_PG: Coax Connection and Power Supply (U1.8), Serializer (R20.1 U5.9)
CAM_SCL: Imager (R5.1 U4.F4), Serializer (U5.4)
CAM_SDA: Imager (R6.1 U4.G3), Serializer (U5.5)
D0: Imager (U4.G7), Serializer (U5.19)
D1: Imager (U4.G6), Serializer (U5.20)
D2: Imager (U4.D9), Serializer (U5.21)
D3: Imager (U4.D10), Serializer (U5.22)
D4: Imager (U4.D7), Serializer (U5.23)
D5: Imager (U4.E7), Serializer (U5.24)
D6: Imager (U4.E9), Serializer (U5.26)
D7: Imager (U4.E8), Serializer (U5.27)
D8: Imager (U4.F6), Serializer (U5.29)
D9: Imager (U4.F7), Serializer (U5.30)
D10: Imager (U4.F9), Serializer (U5.31)
D11: Imager (U4.F8), Serializer (U5.32)
DOUT_P: Coax Connection and Power Supply (L1.2 P1.1), Serializer (C25.1)
FSIN: Imager (U4.F3), Serializer (U5.15)
HSYNC: Imager (U4.B7), Serializer (U5.1)
nRST: Imager (R9.2), Serializer (U5.16)
PCLK: Imager (U4.B6), Serializer (U5.3)
VSYNC: Imager (U4.B8), Serializer (U5.2)
XCLK: Imager (U4.C8), Serializer (R16.2)

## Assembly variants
001: not fitted FID1 FID2 FID3 FID4 FID5 FID6 R8 R24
